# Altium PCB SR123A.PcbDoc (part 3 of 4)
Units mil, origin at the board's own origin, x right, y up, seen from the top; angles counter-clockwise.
Board outline 5500 x 3200 mil, 4 copper layers (Top Layer, Signal Layer 1, Signal Layer 2, Bottom Layer), stack 64.312 mil thick; 295 components, 105 nets, 659 pads, 1365 vias.
Unrouted connection lines stored in the file: 735.
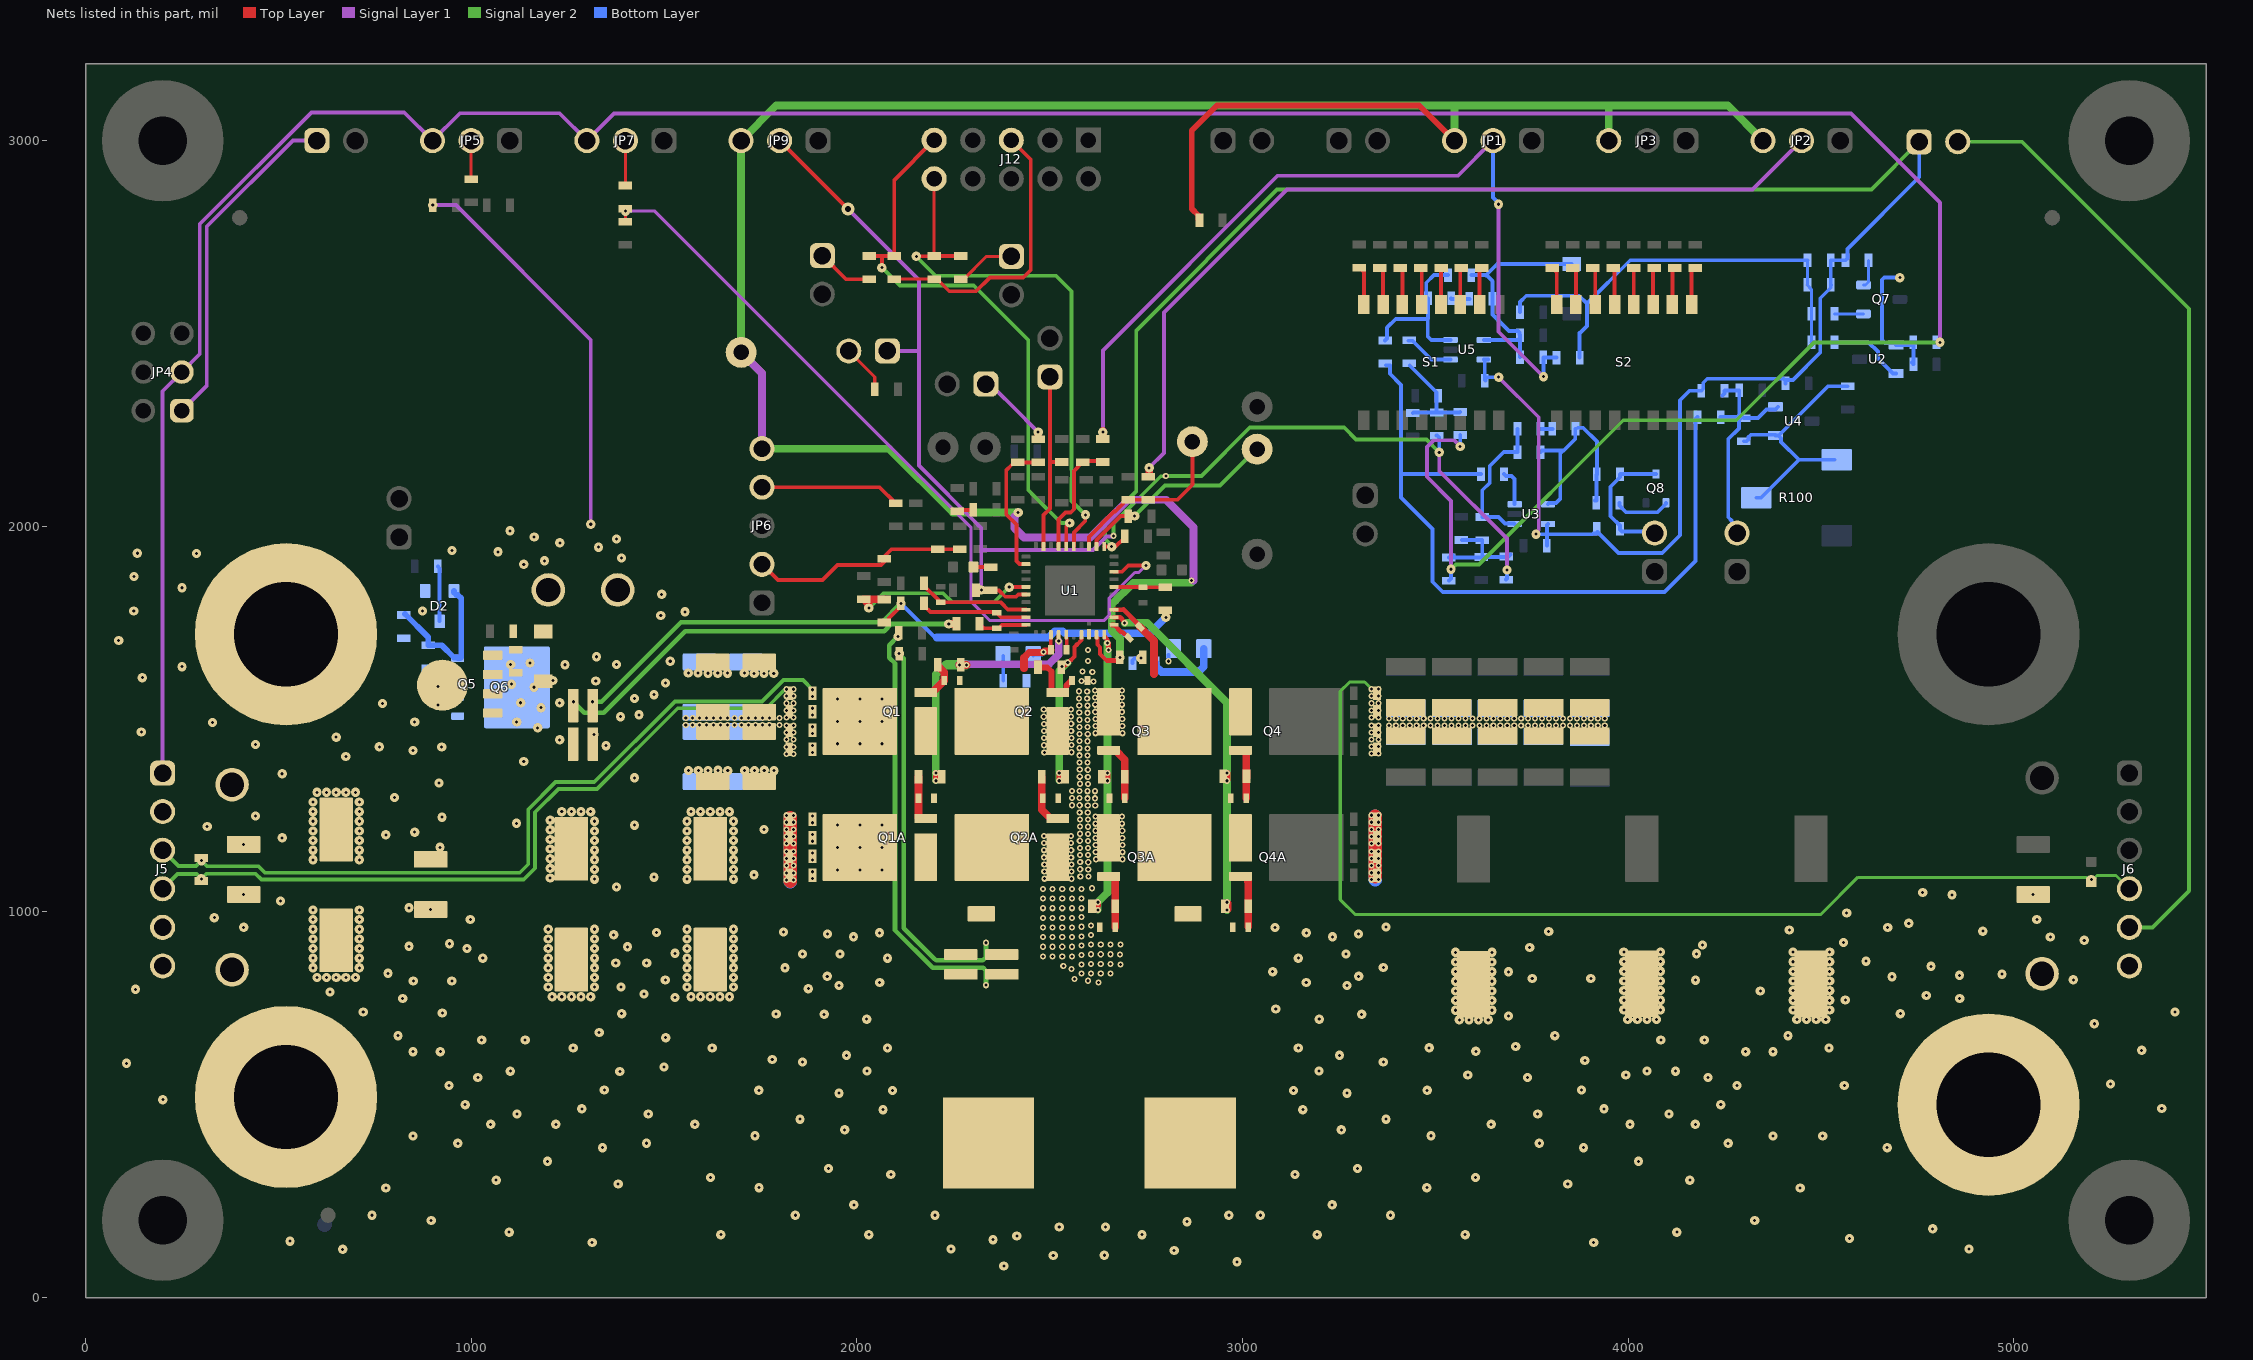
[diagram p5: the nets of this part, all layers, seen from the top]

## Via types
v1: diameter 24, hole 7.87, Top Layer to Bottom Layer, tented both sides, 520 vias
v2: diameter 16, hole 8, Top Layer to Bottom Layer, tented both sides, 418 vias
v3: diameter 24, hole 8, Top Layer to Bottom Layer, tented both sides, 412 vias
v4: diameter 19.68, hole 7.87, Top Layer to Bottom Layer, tented both sides, 12 vias
v5: diameter 16, hole 7.87, Top Layer to Bottom Layer, tented both sides, 2 vias
v6: diameter 34, hole 16, Top Layer to Bottom Layer, tented both sides, 1 vias

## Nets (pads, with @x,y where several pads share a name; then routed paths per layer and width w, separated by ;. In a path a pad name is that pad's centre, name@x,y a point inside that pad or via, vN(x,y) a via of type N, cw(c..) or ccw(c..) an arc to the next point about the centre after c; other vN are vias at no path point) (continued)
GND: C1.1 C2.1 C3.2 C4.2 C5.2 C6.2 C7.2 C8.2 C9.2 C10.2 C11.1 C12.1 C13.1 C14.1 C15.2 C16.2 C17.2 C18.2 C19.2 C20.2 C21.2 C22.2 C23.2 C24.2 C25.1 C26.1 C27.1 C28.1 C29.1 C30.1 C31.2 C32.1 C33.2 C38.1 C56.2 C57.2 C62.2 C63.2 C65.2 C66.2 C67.2 C68.2 C69.2 C70.2 C71.2 C72.2 C73.1 C74.1 C75.1 C76.1 C77.2 C78.1 C79.2 C80.2 C81.1 C82.2 C83.1 C84.1 C85.1 C86.1 J3.1 J4.1 J5.4 J5.5 J5.6 J6.4 J6.5 J6.6 J13.2 NT1.1 Q2.1-2-3 Q2A.1-2-3 Q3.1-2-3 Q3A.1-2-3 R59.1 R60.1 TP3.1 TP4.1 U1.28 | length 8172
  Top Layer w35: C72.2@1827.66,1080.02 C69.2@1827.66,1244.7 ; C86.1@3344.05,1090.88 C83.1@3344.05,1247.76
  Signal Layer 2 w8: v2(3335.03,1577.55) 3335.03,1578 3317.04,1595.99 3277.99,1595.99 3253.8,1571.8 3253.8,1031.76 3291.82,993.73 4500.21,993.73 4596.1,1089.63 5191.78,1089.63 5194.04,1087.37 5208.82,1087.37 5216.03,1094.58 5265.42,1094.58 J6.4@5300,1060
  Signal Layer 2 w10: J5.4@200,1060 238.72,1098.72 287.51,1098.72 296.45,1089.79 v3@298.57,1089.79 ; v3(300.37,1085.82) 313.5,1098.95 441.17,1098.95 456.38,1083.74 1136.51,1083.74 1165.82,1113.04 1165.82,1258.33 1226.42,1318.94 1326.71,1318.94 1535.9,1528.12 1765.18,1528.12 1813.36,1576.3 1816.82,1576.3 v2(1817.97,1577.45) ; J13.2@4855,2997 5022,2997 5455,2564 5455,1054.69 5360.31,960 J6.5@5300,960
  Signal Layer 2 w35: 1827.66,1084 1827.66,1239.65 ; 3344.05,1092.57 3344.05,1247.29
  Bottom Layer w10: R60.1@2715,1645 2715,1652.5 2720,1657.5 2735.71,1657.5 v3(2736.5,1658.29)
  Bottom Layer w35: 1827.66,1077.6 1827.66,1242.29 ; 3344.94,1083.73 3344.94,1248.41
  other v1: 2381.22,81.72 2986.22,92.72 2509.48,108.97 2641.99,109.69 2823.15,121.87 666.81,125 2244.33,125.76 4884.1,125.84 1313.97,142.68 3911.03,142.68 530.5,146.05 2353.42,150 4574.34,152.78 2415,159.39 1647.31,162.88 2031.16,162.88 2739.38,162.88 3193.84,162.88 3577.69,162.88 1098.48,169.61 4126.52,169.61 2525,183 2645.01,183 2856.22,196.72 896.46,199.92 4328.54,199.92 742.62,213.39 2202.79,213.39 2964.88,213.39 3046.49,213.39 1992.24,240.53 3232.76,240.53 778.61,284.09 4446.39,284.09 1746.69,284.82 3478.31,284.82 1381.32,294.2 3843.68,294.2 1064.81,304.3 4160.19,304.3 1620.38,311.03 3604.62,311.03 2088.4,318.88 3136.6,318.88 1926.78,334.6 3298.22,334.6 1198.11,353.33 4026.89,353.33 1340.54,388.47 3884.46,388.47 4671.98,388.47 965.44,400 4259.56,400 849.32,418.78 1735.81,419.5 3489.19,419.5 4375.68,418.78 4504.83,418.78 1968.62,434.98 3256.38,434.98 1050.61,449.08 1219.7,449.08 1579.97,449.08 3645.03,449.08 4005.3,449.08 4174.39,449.08 1852.7,462.55 3372.3,462.55 1118.69,476.02 1459.3,476.02 3765.7,476.02 4106.31,476.02 2068.2,487.23 3156.8,487.23 1287.04,489.49 3937.96,489.49 984.54,500 4240.46,500 200.53,513.05 1953.72,530 3271.28,530 1745.92,537.35 2092.5,536.62 3132.5,536.62 3479.08,537.35 1345.47,538.07 3879.53,538.07 942.62,550.09 4282.38,550.09 4560.87,550.09 5251.11,553.46 1017.39,570.29 3739.31,570.29 4207.61,570.29 3584.42,577.03 3994.2,577.03 1385.54,586.43 1101.66,587 4123.34,587 2026.49,587.72 3198.51,587.72 4048.87,587.72 106.25,607.33 1859.44,610.7 3365.56,610.7 3888.02,614.59 1780.81,617.46 1973.29,627.96 3251.71,627.96 849.32,637.64 920.03,637.64 3605.26,638.36 4304.97,637.64 4375.68,637.64 5331.92,641 1264.7,647.04 1624.97,647.04 2079.91,646.82 3145.09,646.82 4521.1,646.78 3484.38,647.54 3708.61,651 1027.15,667.72 1140.1,667.72 4084.9,667.72 4197.85,667.72 1504.3,673.98 810.19,678.97 3810.23,678.97 4414.81,678.97 1332.04,687.45 2025.72,721.81 3199.28,721.81 3690,730 1915.58,734.34 3309.42,734.34 1790.92,735.31 1390.47,736.03 4705.96,736.1 925.21,737.99 720.17,740.17 3086.48,748.01 4563.53,771.24 822.38,775.68 1528.45,777.78 4773.46,783.29 1448.39,787.2 633.83,792.52 4342.96,795.07 129.82,799.25 1874.48,801 1388.68,805 1953.72,809.36 3271.28,809.36 2059.44,817.2 3165.56,817.2 850.1,820.57 4175.03,822.92 1503.47,823.69 3751.61,827.2 3903.53,827.2 4684.37,831.85 1923.41,832.92 3301.59,832.92 4859.81,835.63 784.65,840.72 3078.42,845 3690,844.75 1813.97,855 3365.56,855.72 4785.38,858.79 1375,867.53 1455.19,867.53 4617.03,872.25 2079.91,880 3145.09,880 1859.44,890.72 1956.61,890.72 3268.39,890.72 4177.57,891.18 1528.45,892.54 3744.81,907.53 1405.69,909.38 838.93,910.72 4193.04,914.38 4558.6,920.84 1991.46,935.32 3233.54,935.32 1369.46,940.58 1924.19,942.54 3300.81,942.54 2059.17,945.72 3165.83,945.72 1480.76,946.61 1809.92,947.98 3794.31,949.38 4418.37,953.06 3084.59,959.38 410,960 4673.26,959.8 3372.3,960.89 4727.94,970.49 334.12,985.13 4567.09,997.36 838.93,1010.72 505.62,1028.16 410,1045.04 5050.72,1045.04 4763.97,1050.49
  other v2: 2626.91,817.29 2599.24,821.5 2564.6,826.41 2582.71,840.11 2607.71,840.11 2632.71,840.11 2657.71,840.11 2556.77,852.03 2535.53,860 2582.74,863.27 2683.73,863.63 2607.71,865.11 2632.71,865.11 2657.71,865.11 2482.79,884.61 2507.79,884.61 2532.79,884.61 2557.79,884.61 2582.74,888.27 2607.71,890.11 2632.71,890.11 2657.71,890.11 2682.52,889.82 2482.79,909.61 2507.79,909.61 2532.79,909.61 2557.79,909.61 2582.74,913.27 2607.71,915.11 2632.71,915.11 2657.71,915.11 2683.73,915.21 2482.79,934.61 2507.79,934.61 2532.79,934.61 2557.79,934.61 2582.76,936.44 2607.71,940.11 2482.79,959.61 2507.79,959.61 2532.79,959.61 2557.79,959.61 2582.76,961.44 2607.71,965.11 2482.79,984.61 2507.79,984.61 2532.79,984.61 2557.79,984.61 2582.76,986.44 2482.79,1009.61 2507.79,1009.61 2532.79,1009.61 2557.79,1009.61 2582.79,1009.61 2482.79,1034.61 2507.79,1034.61 2532.79,1034.61 2557.79,1034.61 2582.79,1034.61 2482.79,1059.61 2507.79,1059.61 2532.79,1059.61 2557.79,1059.61 2582.79,1059.61 2609.87,1061.43 1817.97,1082.45 1835.97,1082.45 3335.03,1083.55 3353.03,1083.55 2486.69,1086.19 2556.89,1085.97 2579.71,1092.24 2600.69,1091.79 1817.97,1100.45 1835.97,1100.45 3335.03,1101.55 3353.03,1101.55 2556.48,1104.42 2486.28,1104.64 2600.28,1110.25 2579.3,1110.7 1817.97,1120 1835.97,1120 3335.03,1120 3353.03,1120 2486.28,1123.13 2556.48,1122.91 2579.3,1129.18 2600.28,1128.74 2620.17,1136.46 2689.29,1136.46 1817.97,1138.45 1835.97,1138.45 3335.03,1138.55 3353.03,1138.55 2555.96,1141.37 2485.76,1141.59 2599.76,1147.19 2578.77,1147.64 2619.76,1154.92 2688.88,1154.91 1817.97,1156.45 1835.97,1156.45 3335.03,1156.55 3353.03,1156.55 2485.76,1160.07 2555.96,1159.86 2578.77,1166.13 2599.76,1165.68 2619.76,1173.41 2688.88,1173.4 1817.97,1177.45 1835.97,1177.45 2555.55,1178.31 3335.03,1177.55 3353.03,1177.55 2485.35,1178.53 2599.35,1184.14 2578.36,1184.58 2619.24,1191.86 2688.36,1191.86 1817.97,1195.45 1835.97,1195.45 3335.03,1195.55 3353.03,1195.55 2485.35,1197.02 2555.55,1196.8 2599.94,1202.26 2578.95,1202.71 2619.24,1210.35 2688.36,1210.35 1817.97,1214 1835.97,1214 3335.03,1214 3353.03,1214 2578.54,1221.16 2599.53,1220.72 2618.83,1228.81 2687.95,1228.8 1817.97,1232.45 1835.97,1232.45 3335.03,1232.55 3353.03,1232.55 2599.53,1239.2 2578.54,1239.65 2618.83,1247.29 2687.95,1247.29 1817.97,1250.45 1835.97,1250.45 3335.03,1250.55 3353.03,1250.55 2578.02,1258.11 2599.01,1257.66 2599.01,1276.15 2618.29,1276.15 2558.2,1276.59 2578.02,1276.59 2557.79,1295.05 2577.61,1295.05 2598.6,1294.61 2617.88,1294.61 2598.6,1313.09 2617.88,1313.09 2557.79,1313.54 2577.61,1313.54 2578.53,1332.23 2599.52,1331.79 2599.11,1350.24 2578.12,1350.69 2578.12,1369.18 2599.11,1368.73 2598.59,1387.19 2577.6,1387.63 2577.6,1406.12 2598.59,1405.68 1817.97,1409.45 1835.97,1409.45 3335.03,1410.55 3353.03,1410.55 2486.27,1413.7 2556.93,1413.99 2598.18,1424.13 2577.19,1424.58 1817.97,1427.45 1835.97,1427.45 3335.03,1428.55 3353.03,1428.55 2485.86,1432.16 2556.52,1432.45 2577.19,1443.07 2598.18,1442.62 1817.97,1447 1835.97,1447 3335.03,1447 3353.03,1447 2485.86,1450.64 2556.52,1450.94 2577.86,1461.28 2598.84,1460.83 2619.22,1463.46 2688.74,1463.46 1817.97,1465.45 1835.97,1465.45 3335.03,1465.55 3353.03,1465.55 2485.34,1469.1 2556,1469.4 2598.43,1479.29 2577.45,1479.74 2618.81,1481.92 2688.33,1481.92 1817.97,1483.45 1835.97,1483.45 1556.46,1484.45 1574.52,1484.45 1592.59,1484.45 1610.65,1484.45 1628.71,1484.45 1646.77,1484.45 1664.83,1484.45 1682.9,1484.45 1700.96,1484.45 1719.02,1484.45 1737.08,1484.45 1755.14,1484.45 1773.21,1484.45 1799.9,1484.45 3335.03,1483.55 3353.03,1483.55 3379.73,1483.55 3397.79,1483.55 3415.85,1483.55 3433.92,1483.55 3451.98,1483.55 3470.04,1483.55 3488.1,1483.55 3506.16,1483.55 3524.23,1483.55 3542.29,1483.55 3560.35,1483.55 3578.41,1483.55 3596.47,1483.55 3614.54,1483.55 3632.6,1483.55 3650.66,1483.55 3668.72,1483.55 3686.78,1483.55 3704.85,1483.55 3722.91,1483.55 3740.97,1483.55 3759.03,1483.55 3777.09,1483.55 3795.16,1483.55 3813.22,1483.55 3831.28,1483.55 3849.34,1483.55 3867.4,1483.55 3885.47,1483.55 3903.53,1483.55 3921.59,1483.55 3939.65,1483.55 2485.34,1487.59 2556,1487.88 2577.45,1498.22 2598.43,1497.78 2618.81,1500.4 2688.33,1500.4 1556.46,1502.45 1574.53,1502.45 1592.59,1502.45 1610.65,1502.45 1628.71,1502.45 1646.77,1502.45 1664.84,1502.45 1682.9,1502.45 1700.96,1502.45 1719.02,1502.45 1737.08,1502.45 1755.15,1502.45 1773.21,1502.45 1799.91,1502.45 3379.73,1501.55 3397.79,1501.55 3415.86,1501.55 3433.92,1501.55 3451.98,1501.55 3470.04,1501.55 3488.1,1501.55 3506.17,1501.55 3524.23,1501.55 3542.29,1501.55 3560.35,1501.55 3578.41,1501.55 3596.48,1501.55 3614.54,1501.55 3632.6,1501.55 3650.66,1501.55 3668.72,1501.55 3686.79,1501.55 3704.85,1501.55 3722.91,1501.55 3740.97,1501.55 3759.03,1501.55 3777.1,1501.55 3795.16,1501.55 3813.22,1501.55 3831.28,1501.55 3849.34,1501.55 3867.41,1501.55 3885.47,1501.55 3903.53,1501.55 3921.59,1501.55 3939.65,1501.55 1817.97,1504.45 1835.97,1504.45 3335.03,1504.55 3353.03,1504.55 2484.93,1506.05 2555.59,1506.34 2597.91,1516.23 2576.93,1516.68 2618.29,1518.86 2687.81,1518.86 1817.97,1522.45 1835.97,1522.45 3335.03,1522.55 3353.03,1522.55 2484.93,1524.53 2555.59,1524.83 2576.93,1535.17 2597.91,1534.72 2618.29,1537.35 2687.81,1537.35 1817.97,1541 1835.97,1541 3335.03,1541 3353.03,1541 2597.5,1553.18 2576.52,1553.62 2617.88,1555.8 2687.4,1555.8 1817.97,1559.45 1835.97,1559.45 3335.03,1559.55 3353.03,1559.55 2576.52,1572.11 2597.5,1571.67 2617.88,1574.29 2687.4,1574.29 1835.97,1577.45 3353.03,1577.55 2582.5,1598.38 2614.13,1597.9 2610.83,1622.29 2585.69,1623.41
  other v3: 4790,178.09 1840.7,213.39 3384.3,213.39 1455,400 3770,400 5383.92,490 1500,597.96 5209.27,710 3562.49,720.07 3587.49,720.07 3612.49,720.07 3637.49,720.07 3999.13,720.95 4024.13,720.95 4049.13,720.95 4074.13,720.95 4437.76,720.74 4462.76,720.74 4487.76,720.74 4512.76,720.74 5418.68,740.17 3552.49,745.07 3647.49,745.07 3989.13,745.95 4084.13,745.95 4427.76,745.74 4522.76,745.74 3552.49,770.07 3647.49,770.07 3989.13,770.95 4084.13,770.95 4427.76,770.74 4522.76,770.74 4860,775.68 1210,780 1235,780 1260,780 1285,780 1310,780 1570,780 1595,780 1620,780 1645,780 1670,780 3552.49,795.07 3647.49,795.07 3989.13,795.95 4084.13,795.95 4427.76,795.74 4522.76,795.74 1200,805 1320,805 1560,805 1680,805 3552.49,820.07 3647.49,820.07 949.88,820.57 3989.13,820.95 4084.13,820.95 4427.76,820.74 4522.76,820.74 5154.65,823.83 600,830 625,830 650,830 675,830 700,830 1200,830 1320,830 1560,830 1680,830 4970,838.59 3552.49,845.07 3647.49,845.07 3989.13,845.95 4084.13,845.95 4427.76,845.74 4522.76,845.74 590,855 710,855 1200,855 1320,855 1560,855 1680,855 3552.49,870.07 3647.49,870.07 3989.13,870.95 4084.13,870.95 4427.76,870.74 4522.76,870.74 590,880 710,880 1030,880 1200,880 1320,880 1560,880 1680,880 3552.49,895.07 3647.49,895.07 3989.13,895.95 4084.13,895.95 4427.76,895.74 4522.76,895.74 590,905 710,905 989.35,905 1200,905 1320,905 1560,905 1680,905 943.56,917.53 5183.02,926.3 590,930 710,930 1200,930 1320,930 1560,930 1680,930 5095,935 4920,950 590,955 710,955 1200,955 1320,955 1560,955 1680,955 590,980 710,980 997.93,980 5060,980 590,1005 710,1005 895,1006.27 4840,1044.28 5201.43,1084.31
  other v5: 2599.26,1650.45 2600,1678.86
HB1: C39.2 U1.25 | length 34.2
  Top Layer w10: U1.25@2543.24,1712.02 2544.6,1710.65 C39.2@2544.6,1680.46 ; C39.2@2544.06,1679.57 2543.73,1679.24 C39.2@2544.86,1680.37
HB2: C40.2 U1.31 | length 56.9
  Top Layer w12: U1.31@2661,1744 2667.59,1744 2686.3,1725.29 2690.19,1725.29 2703.34,1712.14 C40.2@2704.68,1712.14
HO1: R11.1 R61.1 U1.24 | length 748.9
  Top Layer w10: R61.1@2213.36,1350.64 2205,1342.28 R61.1@2220,1350 ; U1.24@2523.47,1718.83 2523.55,1718.75 2523.55,1702.16 v2(2523.73,1701.99)
  Top Layer w15: v2@2205,1342.28 v2(2205,1360)
  Top Layer w20: v2(2265.93,1640.48) v2@2284.35,1640.48
  Signal Layer 1 w20: v2@2265.93,1642.11 2284.51,1642.11 2498.33,1642.11 2523.73,1667.51 v2(2523.73,1701.99)
  Signal Layer 2 w10: 2231.39,1642.11 2233.01,1640.48
  Signal Layer 2 w20: v2@2205,1341.18 v2(2205,1360) 2205,1615.72 2231.39,1642.11
  Signal Layer 2 w25: 2233.01,1640.48 v2(2265.93,1640.48) v2@2283.21,1640.48
  other v2: 2205,1340 2284.51,1640.64
HO1_G: C55.1 Q1.4 R11.2 | length 112.7
  Top Layer w20: Q1.4@2178.9,1569 2196.61,1569 2198.43,1570.81 2198.43,1571.53 C55.1@2227.09,1600.2 2227.09,1621.8 2215.37,1633.52 2209.9,1633.52 R11.2@2209.9,1641.02
HO2: R14.1 R36.1 U1.32 | length 981.4
  Top Layer w10: U1.32@2667.17,1764.1 U1.32@2667.25,1764.02 ; 2680.79,1764.02 2680.98,1763.83 ; R14.1@2950.59,1351.86 v2@2962,1341.42
  Top Layer w11: U1.32@2667.25,1764.02 2680.79,1764.02
  Top Layer w12: 2680.98,1763.83 2682.96,1763.83 2694,1752.79 2694,1749.98 v2(2694.76,1749.22)
  Top Layer w15: v2@2962,1341.42 v2@2962,1360.76
  Top Layer w20: R36.1@2955,1015 R36.1@2955,1022.36 ; R36.1@2962,1007.64 R36.1@2962,1022.36
  Signal Layer 2 w20: v2(2694.76,1749.22) 2695.46,1749.91 2752.84,1749.91 2960,1542.75 v2(2960,1025) v2(2960,1005)
  other v2: 2960,1340 2960,1360
HO2_G: C58.2 Q4.4 R14.2 | length 138.1
  Top Layer w20: Q4.4@2995.1,1419 3008.19,1419 3010,1417.19 3010,1365.81 3010.59,1365.22 R14.2@3010.59,1348.4 ; C58.2@3010,1295 R14.2@3010,1348.4
ILIMCOMP: C45.1 JP9.2 JP10.1 R56.2 R79.2 R94.2 U1.16 | length 3417.5
  Top Layer w10: JP9.2@1800,3000 v6(1977.44,2822.56) ; C45.1@2309.35,1834.12 R56.2@2347.75,1834.12 2368.48,1834.12 2370.51,1832.09 2370.51,1831.89 2385.08,1817.32 2412.73,1817.32 2418.56,1823.16 U1.16@2438.83,1823.16
  Signal Layer 1 w10: v6(1977.44,2822.56) 2161.08,2638.92 2161.08,2454.69 ; JP10.1@2079.27,2454.69 2161.08,2454.69 ; v1(2322.86,1834.45) 2322.86,1938.05 ; v2@2664.71,1974.26 2663.57,1973.11 2647.55,1973.11 2612.48,1938.05 2322.86,1938.05 ; v1(3510.4,2191.74) 3510.4,2143.71 3686.21,1967.9 v1(3686.21,1886.67) ; 2161.08,2454.69 2161.08,2157.46 2314.6,2003.94 2314.6,2003.4 2322.86,1995.15 2322.86,1938.05
  Signal Layer 2 w10: v2(2665.31,1975.22) 2665.31,2006.58 2671.11,2012.38 2788.33,2129.6 2800.21,2129.6 v2(2801.36,2130.75) 2893.97,2130.75 3019.1,2255.87 3263.95,2255.87 3294.68,2225.14 3477,2225.14 v1(3510.4,2191.74)
  Bottom Layer w10: R94.2@3503.34,2235.08 3505.4,2235.08 3510.4,2230.08 v1(3510.4,2191.74) ; R79.2@3683.97,1861.54 3686.21,1863.78 v1(3686.21,1886.67)
ISNSN: C49.1 R6.1 U1.19 | length 282.9
  Top Layer w10: R6.1@2174.38,1800 2174.38,1793.86 2190.87,1777.37 2361.06,1777.37 C49.1@2362.79,1775.65 2374.33,1764.1 U1.19@2438.83,1764.1
ISNSP: C49.2 R5.1 U1.20 | length 128.8
  Top Layer w10: R5.1@2318.38,1747 2329.73,1735.65 C49.2@2362.79,1735.65 2368.01,1735.65 2376.78,1744.42 U1.20@2438.83,1744.42
LO1: R12.1 R62.1 U1.27 | length 457.2
  Top Layer w10: v2@2525,1342.28 2533.86,1351.14 v2(2525,1360) ; 2571.71,1693.9 2582.53,1704.73 U1.27@2582.53,1712.02
  Top Layer w11: v2(2547.06,1646.28) 2548.12,1646.28 2556.01,1654.16 2556.77,1654.16 2564.6,1662 2564.6,1686.8 2571.71,1693.9
  Top Layer w15: v2@2525,1342.28 v2(2525,1360) ; R12.1@2533,1635 2540,1642 2540,1641.6 2542.5,1644.1 2544.62,1644.1 2546.79,1646.28 v2(2547.06,1646.28)
  Signal Layer 2 w20: v2@2525,1342.28 v2(2525,1360) 2525,1625 2546.28,1646.28 v2(2547.06,1646.28)
  other v2: 2525,1340 2531.69,1636.61
LO1_G: C56.1 Q2.4 R12.2 | length 164.7
  Top Layer w15: R12.2@2470,1634.1 2494.07,1634.1 2504.63,1623.54 2504.63,1573.31 2508.94,1569 2538.61,1569 2542.93,1573.31 2542.93,1586.71 2551.71,1595.5 2555,1595.5 C56.1@2555,1600
LO2: R13.1 R63.1 U1.30 | length 790.6
  Top Layer w10: R13.1@2644.68,1340.32 v2@2650,1340.32
  Top Layer w12: U1.30@2642.66,1713.02 2649.67,1706.01 v2(2649.67,1696.91) v2@2648.9,1697.68 ; v2@2652.63,1679.24 2652.67,1679.29 v2@2652.67,1697.88
  Top Layer w15: v2(2625,1005.32) 2618.48,1011.83 2615.16,1015.16 v2(2625,1025) ; v2@2650,1340.32 v2(2650,1360)
  Signal Layer 2 w20: v2(2625,1005.32) v2(2625,1025) 2650,1050 2650,1340.32 v2@2650,1676.61 ; v2@2649.67,1679.58 v2(2649.67,1696.91)
  other v2: 2650,1340 2652.63,1679
LO2_G: C57.1 Q3.4 R13.2 | length 151.7
  Top Layer w20: Q3.4@2653.1,1419 2670.82,1419 2695,1394.82 R13.2@2695,1350 C57.1@2695,1295
MODE: C52.1 R22.2 U1.7 | length 305.2
  Top Layer w10: U1.7@2523.47,1947.17 2523.47,2017.67 2535.88,2030.07 2541.68,2035.87 2554.72,2035.87 2562.84,2044 2562.84,2143.53 C52.1@2585.69,2166.38 ; C52.1@2585.69,2169.38 2637.96,2169.38 R22.2@2638.15,2169.57
MODE1: JP1.2 R22.1 R67.1 R75.1 | length 2217.1
  Top Layer w8: R22.1@2638.15,2229.57 R22.1@2638.59,2229.13
  Top Layer w20: R22.1@2638.15,2229.57 v1@2638.15,2246.91
  Signal Layer 1 w10: v1(2638.15,2243.91) 2638.15,2456.08 3090.96,2908.89 3558.89,2908.89 JP1.2@3650,3000 ; v3(3664.21,2834.97) 3664.21,2504.54 v1(3780.95,2387.8)
  Bottom Layer w10: JP1.2@3650,3000 3650,2852.97 3664.21,2838.76 v3(3664.21,2834.97) ; R67.1@3780.48,2438.06 3780.48,2388.27 v1(3780.95,2387.8) ; R67.1@3782.03,2438.5 3783.03,2437.5 R75.1@3814.53,2437.5
NetC3_1: C3.1 C4.1 C5.1 C6.1 C7.1 C8.1 C9.1 C10.1 C25.2 C26.2 C31.1 C65.1 C66.1 C67.1 C68.1 C69.1 C70.1 C71.1 C72.1 J5.3 Q1.5-6-7-8 Q1A.5-6-7-8 R1.2 R2.2 R6.2 R9.2 R15.2 R34.2 TP8.1 | length 4797.6
  Top Layer w10: R9.2@2071.17,1750.32 2078.67,1750.32 2083.67,1755.32 2083.67,1761.79 2114.38,1792.5 v1(2114.38,1800)
  Top Layer w20: v1(2801.36,1763.92) R34.2@2801.36,1780.84
  Signal Layer 1 w10: v3(900.36,2832.68) 960.36,2832.68 1310.08,2482.95 v3(1310.08,2005.2)
  Signal Layer 2 w10: J5.3@200,1160 241.28,1118.72 286.65,1118.72 v3(300.78,1132.86) 315.29,1118.35 448.57,1118.35 465.31,1101.61 1126.13,1101.61 1147.94,1123.42 1147.94,1265.73 1219.02,1336.81 1319.31,1336.81 1528.49,1545.99 1754.53,1545.99 1809.61,1601.07 1860.23,1601.07 v2(1885.18,1576.12)
  Signal Layer 2 w12: v3(1315,1545) 1337.91,1545 1544.23,1751.32 2065.69,1751.32 v1(2114.38,1800)
  Bottom Layer w10: v1(2114.38,1800) 2203.04,1711.33 2207.67,1711.33
  Bottom Layer w20: 2207.67,1711.33 2496.48,1711.33 2513.01,1727.86 2534.44,1727.86 2539.52,1722.79 2760.23,1722.79 v1(2801.36,1763.92)
  other v1: 1377.21,1064.39 1474.3,1090 1733.39,1096.1 1759.38,1214 1423.63,1224.87
  other v2: 1885.18,1086.12 1885.18,1104.12 1885.18,1135.12 1885.18,1153.12 1885.18,1183.12 1885.18,1201.12 1885.18,1231.12 1885.18,1249.12 1885.18,1413.12 1885.18,1431.12 1885.18,1462.12 1885.18,1480.12 1885.18,1510.12 1885.18,1528.12 1885.18,1558.12
  other v3: 1320,1085 1560,1085 1680,1085 1205,1087.91 1950.16,1109.13 2008.03,1109.13 2065.91,1109.13 1320,1110 1560,1110 1680,1110 1205,1112.91 1320,1135 1560,1135 1680,1135 1205,1137.91 1320,1160 1560,1160 1680,1160 1205,1162.91 1950.16,1167 2008.03,1167 2065.91,1167 1320,1185 1560,1185 1680,1185 1205,1187.91 1320,1210 1560,1210 1680,1210 1205,1212.91 1950.16,1224.87 2008.03,1224.87 2065.91,1224.87 1320,1235 1560,1235 1680,1235 1205,1237.91 1235,1260 1260,1260 1285,1260 1310,1260 1570,1260 1595,1260 1620,1260 1645,1260 1670,1260 1423.63,1347.62 1665.43,1366.2 1785.43,1366.2 1563.86,1366.94 1589.16,1366.94 1614.46,1366.94 1639.94,1367.13 1709.16,1366.94 1734.46,1366.94 1759.94,1367.13 1349.69,1431.12 1950.16,1436.13 2008.03,1436.13 2065.91,1436.13 1318.54,1459.82 1950.16,1494 2008.03,1494 2065.91,1494 1387.04,1506.22 1435,1511.03 1950.16,1551.87 2008.03,1551.87 2065.91,1551.87 1423.63,1553.23 1474.3,1563.24 1504.28,1593.64 1323.18,1598.59 1733.9,1618.38 1614.06,1618.87 1639.54,1619.06 1664.84,1619.06 1708.41,1619.31 1759.38,1618.56 1784.68,1618.56 1563.27,1619.8 1588.57,1619.8 1376.98,1641.81 1516.34,1649.96 1325,1661.68 1491.71,1768.7 1554.27,1778.23 1493.96,1823.54 1390,1917.71 1330.15,1945.95 1377.21,1967.19
NetC34_2: C34.2 R34.1 U1.36 | length 133.5
  Top Layer w10: U1.36@2667.17,1842.84 2741.47,1842.84 C34.2@2742.37,1841.95 R34.1@2800.28,1841.92
NetC35_1: C35.1 R35.1 U1.18 | length 291.6
  Top Layer w10: R35.1@2174.47,1852.68 2174.47,1844.92 2186.39,1833 2186.65,1833 2189.28,1830.37 2189.71,1830.37 2197.25,1822.83 C35.1@2216.93,1803.16 ; C35.1@2222.79,1803.16 2372.95,1803.16 2380.08,1796.02 2387.66,1788.48 ; 2387.66,1788.44 2392.32,1783.79 U1.18@2438.83,1783.79
NetC42_1: C42.1 R32.1 | length 37.6
  Top Layer w10: C42.1@2264.56,2042.59 R32.1@2302.19,2042.59
NetC46_1: C46.1 R56.1 | length 45.5
  Top Layer w10: C46.1@2302.69,1894.12 R56.1@2347.75,1894.12 ; C46.1@2312.38,1894.43 C46.1@2312.69,1894.12
NetC50_1: C50.1 JP6.2 R19.1 R20.2 | length 570.6
  Top Layer w10: JP6.2@1754.31,1901.32 1795.25,1860.37 1911.32,1860.37 1950.45,1899.51 2062.86,1899.51 2072.77,1909.41 2072.77,1923.56 2089.63,1940.42 C50.1@2209.91,1940.42 R20.2@2266.51,1940.42
NetC59_1: C59.1 R59.2 | length 63.6
  Bottom Layer w10: R59.2@2380,1600 C59.1@2380,1663.57
NetC60_1: C60.1 R60.2 | length 190.7
  Bottom Layer w20: R60.2@2775,1645 2775,1637.5 2790.37,1622.13 2885.74,1622.13 2899.7,1636.09 C60.1@2899.7,1682.46
NetC61_1: C61.1 Q1A.4 R61.2 | length 125.8
  Top Layer w20: R61.2@2160,1350 2160,1243.81 2161.81,1242 Q1A.4@2178.9,1242
NetC62_1: C62.1 Q2A.4 R62.2 | length 135.3
  Top Layer w20: R62.2@2480,1350 2480,1295 2480,1265.18 2503.18,1242 Q2A.4@2520.9,1242
NetC63_1: C63.1 Q3A.4 R63.2 | length 147.8
  Top Layer w20: Q3A.4@2653.1,1092 2668.19,1092 2670,1090.19 R63.2@2670,1015 C63.1@2670,960
NetC64_2: C64.2 Q4A.4 R36.2 | length 148.6
  Top Layer w20: Q4A.4@2995.1,1092 3012.82,1092 3014.63,1090.19 3014.63,1078.84 3015,1078.47 3015,1028.36 3015,1002 C64.2@3015,962
NetC87_1: C87.1 D2.2 Q6.4 R58.1 | length 388.6
  Bottom Layer w15: C87.1@828.43,1772.55 888.6,1712.39 R58.1@888.6,1691.7 923.95,1691.7 955.61,1660.04 962.5,1660.04 Q6.4@965.04,1657.5 971.62,1657.5 974.16,1660.04 974.16,1813.31 965.37,1822.09 961.85,1822.09 955.57,1828.37 D2.2@955.57,1832.31
NetC88_2: C88.2 D2.3 | length 144
  Bottom Layer w10: C88.2@913.6,1895.71 918.17,1891.14 D2.3@918.17,1753.57
NetC89_2: C89.2 R71.1 R72.2 R73.2 R74.2 R75.2 | length 1200.6
  Bottom Layer w8: C89.2@4465.53,2689.74 4465.53,2627.5 4464.04,2626 4475.53,2614.5 R73.2@4475.53,2550.81 4475.53,2478.5 R72.2@4474.04,2477
  Bottom Layer w10: R74.2@3720.01,2555 3720.01,2582 3735.94,2597.93 3873.6,2597.93 3893.78,2577.76 ; R75.2@3874.53,2437.5 3874.53,2501 ; 3875.03,2501 3893.78,2519.74 3893.78,2577.76 ; C89.2@4465.53,2689.74 4005.76,2689.74 3893.78,2577.76
NetC91_1: C91.1 R81.2 R84.1 U3.1 | length 378.5
  Bottom Layer w10: U3.1@3705.87,2005.92 3704.61,2007.18 3680.5,2007.18 3663.68,2024 R81.2@3622.03,2024 3622.03,2093.29 3641.41,2112.67 3641.41,2155.87 3677.74,2192.2 R84.1@3713.14,2192.2 C91.1@3713.14,2252.71
NetC91_2: C91.2 R83.2 | length 30.7
  Bottom Layer w10: C91.2@3773.14,2252.71 R83.2@3803.8,2252.71
NetC95_1: C95.1 R97.2 R99.1 U5.3 | length 418.7
  Bottom Layer w10: R97.2@3370.03,2482 3375.03,2487 3375.03,2515 3397.53,2537.5 3480.53,2537.5 ; R99.1@3533.35,2651.3 3496.7,2651.3 3476.84,2631.43 3476.84,2595.13 C95.1@3481.23,2590.74 3481.23,2538.19 3480.53,2537.5 ; U5.3@3539.73,2483.38 3489.57,2483.38 3480.53,2492.42 3480.53,2537.5
NetC95_2: C95.2 R98.2 | length 47.7
  Bottom Layer w10: C95.2@3541.23,2590.74 3542.17,2589.8 R98.2@3588.52,2589.8
NetD1_2: D1.2 Q5.4 R38.2 R39.1
NetD3_1: D3.1 R66.2 R67.2 R98.1 R99.2 U5.4 | length 629.9
  Bottom Layer w10: R99.2@3593.35,2651.3 3632.81,2651.3 3648.52,2635.58 R98.1@3648.52,2589.8 3648.52,2549.01 3691.33,2506.21 3715.01,2506.21 3718.53,2502.68 R66.2@3718.53,2497.5 ; U5.4@3626.34,2483.38 3715.01,2483.38 R66.2@3720.01,2488.38 ; 3631.03,2650 3661,2679.97 D3.1@3853.53,2679.97 ; R67.2@3720.01,2438.95 3720.01,2483.38 R66.2@3720.01,2495.58
NetJ10_1: J10.1 R25.2 | length 205.9
  Top Layer w20: R25.2@2470.36,2225.85 v1(2470.36,2244.37)
  Signal Layer 1 w10: J10.1@2334.52,2368.9 2355.06,2348.36 2366.37,2348.36 2404.73,2310 v1(2470.36,2244.37)
NetJ16_2: J16.2 Q8.3 R85.1 R87.2 | length 350.7
  Bottom Layer w10: J16.2@4068.96,1982.51 4064.98,1986.48 3984.16,1986.48 3979.16,1991.48 R87.2@3979.16,1994.11 3979.16,2001.61 3954.8,2025.97 3954.8,2102.65 3979.16,2127.01 R85.1@3979.16,2134.51 3980.47,2135.81 Q8.3@4072.59,2135.81
NetJP5_2: JP5.2 R16.2 | length 100
  Top Layer w8: R16.2@1000,2900 JP5.2@1000,3000
NetJP7_2: JP7.2 R37.2 | length 116.3
  Top Layer w8: R37.2@1400,2883.75 JP7.2@1400,3000
NetJP10_2: JP10.2 R26.2 | length 126.8
  Top Layer w8: JP10.2@1979.27,2454.69 2046.66,2387.3 R26.2@2046.66,2355.82
NetJP11_1: JP11.1 R27.1 | length 147.3
  Top Layer w10: JP11.1@1910.65,2702 1971.91,2640.73 R27.1@2032.57,2640.73
NetJP12_1: JP12.1 R28.1 | length 156.9
  Top Layer w8: R28.1@2269.93,2640.85 2277.43,2640.85 2336.52,2699.94 JP12.1@2401.09,2699.94 JP12.1@2400.18,2700.85
NetL1_1: L1.1 R3.2 R4.2 R8.2 | length 1094.1
  Signal Layer 2 w12: v3(2106.66,1714.26) 2084.13,1691.73 2084.13,1659.28 2099.04,1644.37 2099.04,952.73 2196.76,855 2327.45,855 2335,847.45 v2(2335,810)
NetQ7_1: Q7.1 R73.1 | length 74.9
  Bottom Layer w8: R73.1@4535.53,2550.81 Q7.1@4610.4,2550.81
NetQ7_2: Q7.2 R76.2 | length 72.9
  Bottom Layer w8: Q7.2@4610.4,2625.62 4615.99,2625.62 4623.66,2633.28 R76.2@4623.66,2689.74
NetQ8_1: Q8.1 R86.2 | length 146.8
  Bottom Layer w10: R86.2@3977.68,2061.01 3977.68,2053.51 3994.86,2036.32 4076.05,2036.32 4098.18,2058.45 Q8.1@4098.18,2061.01
NetR9_1: R9.1 R10.2 U1.15 | length 528.6
  Top Layer w10: v1(2395.38,1842.19) 2396.03,1842.84 U1.15@2438.83,1842.84
  Top Layer w20: R10.2@2017.44,1811.01 R10.2@2024.94,1811.01 ; v1(2031.26,1788.24) 2030.49,1789 2030.49,1797.96 2024.94,1803.51 R10.2@2024.94,1811.01 ; R9.1@2071.17,1811.13 2025.06,1811.13 R10.2@2024.94,1811.01
  Signal Layer 2 w10: v1(2031.26,1788.24) 2069.43,1826.4 2223.76,1826.4 2247,1803.16 2356.34,1803.16 v1(2395.38,1842.19)
NetR40_2: R40.2 S1.2 | length 97.5
  Top Layer w10: S1.2@3615,2575 3615,2664 R40.2@3621,2670
NetR41_2: R41.2 S1.3 | length 96.2
  Top Layer w10: S1.3@3565,2575 3565,2667 R41.2@3568,2670
NetR42_2: R42.2 S1.4 | length 95
  Top Layer w10: S1.4@3515,2575 R42.2@3515,2670
NetR43_2: R43.2 S1.5 | length 96.2
  Top Layer w10: R43.2@3462,2670 3465,2667 S1.5@3465,2575
NetR44_2: R44.2 S1.6 | length 97.5
  Top Layer w10: R44.2@3409,2670 3415,2664 S1.6@3415,2575
NetR45_2: R45.2 S1.7 | length 98.7
  Top Layer w10: R45.2@3356,2670 3365,2661 S1.7@3365,2575
NetR46_2: R46.2 S1.8 | length 100.2
  Top Layer w10: R46.2@3303.61,2670.47 3315,2659.08 S1.8@3315,2575
NetR47_2: R47.2 S2.1 | length 98.7
  Top Layer w10: S2.1@4165,2575 4165,2661 R47.2@4174,2670
NetR48_2: R48.2 S2.2 | length 97.5
  Top Layer w10: S2.2@4115,2575 4115,2664 R48.2@4121,2670
NetR49_2: R49.2 S2.3 | length 96.2
  Top Layer w10: S2.3@4065,2575 4065,2667 R49.2@4068,2670
NetR50_2: R50.2 S2.4 | length 95
  Top Layer w10: S2.4@4015,2575 R50.2@4015,2670
NetR51_2: R51.2 S2.5 | length 96.2
  Top Layer w10: R51.2@3962,2670 3965,2667 S2.5@3965,2575
NetR52_2: R52.2 S2.6 | length 97.5
  Top Layer w10: R52.2@3909,2670 3915,2664 S2.6@3915,2575
NetR53_2: R53.2 S2.7 | length 98.7
  Top Layer w10: R53.2@3856,2670 3865,2661 S2.7@3865,2575
NetR54_2: R54.2 S2.8 | length 100
  Top Layer w10: R54.2@3803,2670 3815,2658 S2.8@3815,2575
NetR69_1: R69.1 R70.2 U2.1 | length 358.2
  Bottom Layer w10: v1(4704.85,2644.7) 4704.26,2645.29 4664.48,2645.29 4658.63,2639.43 4658.63,2483.51 4667.56,2474.58 4691.02,2474.58 U2.1@4695.06,2470.54 4734.74,2470.54 4739.74,2475.54 R69.1@4739.74,2477 4739.87,2476.87 4739.87,2420.13 4739.74,2420 R70.2@4740,2420 R70.2@4735.74,2424.26
NetR72_1: R72.1 U2.2 | length 203.9
  Bottom Layer w10: R72.1@4535.53,2477 4623.6,2477 4647.81,2452.79 4647.81,2435.11 4687.18,2395.74 U2.2@4695.06,2395.74 ; R72.1@4537.03,2477 R72.1@4537.27,2477.24
NetR77_1: R77.1 R78.1 R79.1 R80.2 R81.1 | length 266.8
  Bottom Layer w10: R78.1@3535.68,1919.01 R78.1@3541.77,1919.01 ; R78.1@3546.77,1924.01 R78.1@3541.77,1919.01 ; R80.2@3569.03,1964 3569.28,1964.25 3621.78,1964.25 R81.1@3622.03,1964 3622.03,1923.5 R77.1@3618.03,1919.5 ; R77.1@3618.17,1919.01 R78.1@3541.77,1919.01 ; R77.1@3619.66,1920.5 3689,1920.5 R79.1@3695.04,1926.54
NetR82_2: R82.2 U3.3 | length 98
  Bottom Layer w10: R82.2@3678.53,2135.5 3683.53,2130.49 3697.68,2130.49 3705.87,2122.29 U3.3@3705.87,2057.1
NetR83_1: R83.1 R84.2 R85.2 R86.1 U3.4 | length 512
  Bottom Layer w10: R84.2@3773.14,2192.2 3777.16,2196.22 3833.21,2196.22 3863.06,2226.07 3863.06,2251.98 R83.1@3863.8,2252.71 ; U3.4@3792.48,2057.1 3795.36,2059.97 3812.86,2059.97 3824.06,2071.17 3824.06,2188.52 3830.03,2194.5 ; R83.1@3870.06,2255.51 3883.53,2255.51 3919.16,2219.87 R85.2@3919.16,2134.51 3918.42,2133.76 R86.1@3918.42,2066.5 ; R86.1@3914.3,2066.74 R86.1@3914.53,2066.5
NetR89_2: R89.2 R90.1 R100.1 R100.2 U4.1 | length 665.3
  Bottom Layer w10: R89.2@4300.18,2220.51 4307.68,2220.51 4312.68,2225.51 4312.68,2231.64 4318.53,2237.5 U4.1@4382.29,2237.5 ; R100.2@4332.87,2074.07 4344.68,2074.07 4443.11,2172.5 ; U4.1@4392.57,2237.5 4518.07,2363.01 R90.1@4569.18,2363.01 ; 4452.53,2172.5 4443.11,2172.5 ; 4452.76,2172.5 R100.1@4536.03,2172.5 ; U4.1@4390.16,2235.1 U4.1@4382.29,2235.1 U4.1@4390.16,2235.1 ; U4.1@4390.16,2235.1 4396.98,2228.29 4396.98,2218.63 4443.11,2172.5
NetR92_1: R92.1 R93.1 R94.1 R95.2 R96.1 | length 274.9
  Bottom Layer w10: R96.1@3434.03,2417 3503.34,2347.69 R94.1@3503.34,2295.08 ; R92.1@3441.84,2293.59 3443.33,2295.08 R94.1@3503.34,2295.08 ; R93.1@3564.83,2296.56 3563.35,2295.08 R94.1@3503.34,2295.08
NetR96_2: R96.2 U5.1 | length 129.4
  Bottom Layer w10: R96.2@3430.53,2481 3441.03,2481 3489.83,2432.2 U5.1@3539.73,2432.2
nRST: R37.1 R57.1 U1.38 | length 2104.7
  Top Layer w8: R57.1@1400,2790 v3(1400,2817.24)
  Top Layer w10: U1.38@2667.17,1882.21 2687.71,1882.21 2704.03,1898.53 v1(2750.08,1898.53)
  Signal Layer 1 w8: v3@1400.22,2817.24 1476.03,2817.24 2296.73,1996.53 2296.73,1804.08 2345.67,1755.14 2640.53,1755.14 2654.76,1769.37 2654.76,1813.55 2721.2,1879.99 2731.55,1879.99 v1(2750.08,1898.53)
R_FB: JP6.4 R18.2 | length 363.2
  Top Layer w10: JP6.4@1754.31,2101.32 2059.1,2101.32 R18.2@2100.43,2059.98
RT: R25.1 R30.2 U1.12 | length 365.9
  Top Layer w10: U1.12@2438.83,1901.9 2421.54,1901.9 2413.87,1909.56 2413.87,2004.64 2387.43,2031.08 2387.43,2144.99 2403.19,2160.75 2412.36,2160.75 R30.2@2417.36,2165.75 R25.1@2470.26,2165.75
SCL: J12.9 R27.2 R64.1 U1.6 | length 1493
  Top Layer w10: R27.2@2032.57,2700.73 2032.63,2700.79 2065.11,2700.79 ; v1(2065.04,2670.6) 2065.04,2700.73 2065.11,2700.79 ; J12.9@2200.67,3001.23 2097.33,2897.9 2097.33,2701.04 R64.1@2097.58,2700.79 2065.11,2700.79 ; U1.6@2543.16,1947.17 2543.16,1999.36 v1(2552.04,2008.24)
  Signal Layer 2 w10: v1(2065.04,2670.6) 2069.31,2666.33 2070.8,2666.33 2112.31,2624.82 2303.38,2624.82 2444.73,2483.47 2444.73,2093.71 2459.62,2078.82 2530.2,2008.24 v1(2552.04,2008.24)
SDA: J12.10 R28.2 R65.1 U1.5 | length 1440.2
  Top Layer w8: R65.1@2200.67,2701.1 J12.10@2200.67,2901.23
  Top Layer w10: v1(2154.38,2699.94) 2154.83,2700.4 2199.96,2700.4 R65.1@2200.42,2700.85 ; R65.1@2200.67,2701.1 R65.1@2200.42,2700.85 ; R28.2@2269.93,2700.85 R65.1@2200.42,2700.85 ; U1.5@2562.84,1947.17 2562.84,1983.86 2592.37,2013.39 v1@2592.37,2023.59
  Signal Layer 2 w10: v1(2154.38,2699.94) 2204.59,2649.73 2516.89,2649.73 2557.24,2609.37 2557.24,2146.6 2557.35,2146.5 2557.35,2125.89 2557.24,2125.79 2557.24,2065.74 v1(2593.31,2029.67)
SLOPE: JP8.1 R29.2 U1.9 | length 468
  Top Layer w10: U1.9@2484.1,1947.17 2484.1,2028.85 2500.64,2045.39 2500.64,2166.52 ; JP8.1@2500.64,2377.56 2500.64,2166.52 ; R29.2@2531.4,2166.52 2500.64,2166.52
SS/ATRK: C44.1 TP12.1 U1.2 | length 533.4
  Top Layer w10: U1.2@2621.9,1947.17 2621.9,1964.49 2684.02,2026.62 v1(2720.52,2026.62)
  Signal Layer 2 w10: v1(2720.52,2026.62) 2799.36,2105.46 2941.66,2105.46 3035.67,2199.46 TP12.1@3040.7,2199.46
SW1: C39.1 C55.2 C59.2 C61.2 Q1.1-2-3 Q1A.1-2-3 Q2.5-6-7-8 Q2A.5-6-7-8 R3.1 R4.1 R7.2 TP5.1 U1.23 | length 1202.7
  Top Layer w10: C39.1@2502.85,1674.78 C39.1@2503.11,1674.52 ; C39.1@2502.85,1687.37 2502.85,1711.16 U1.23@2503.71,1712.02
  Top Layer w18: 2433.41,1659.03 2446.65,1672.27 2468.85,1672.27 2482.58,1672.27 2486.85,1676.54 C39.1@2502.23,1676.54 ; v2@2482.5,1672.27 v2(2484.17,1673.94) ; 2492.75,1676.54 C39.1@2502.23,1676.54 ; C39.1@2503.73,1679.54 2503.73,1678.04 C39.1@2502.23,1676.54
  Top Layer w20: 2433.41,1632.17 2433.41,1659.03
  Signal Layer 2 w12: v3(2110,1670) 2110,1668.95 2121.98,1656.97 2121.98,958.02 2202.62,877.38 ; 2205.63,875 2327.07,875 2335,882.93 v2(2335,920)
  Bottom Layer w10: C59.2@2457.57,1664.74 2457.57,1665.95 C59.2@2463.31,1671.68 ; C59.2@2457.57,1665.36 2465.24,1673.03 v2@2480.67,1673.03 ; v2@2482.58,1672.27 2481.43,1672.27 2480.56,1673.13 2484.74,1673.94 v2(2484.17,1673.94)
  Bottom Layer w20: C59.2@2464.46,1672.25 v2@2479.89,1672.25
SW2: C40.1 C58.1 C60.2 C64.1 L1.2 Q3.5-6-7-8 Q3A.5-6-7-8 Q4.1-2-3 Q4A.1-2-3 TP6.1 U1.33 | length 240.7
  Top Layer w12: U1.33@2667.25,1783.71 2691.91,1783.71
  Top Layer w13: 2691.91,1783.71 2726.85,1748.77 2726.85,1747.85 C40.1@2734.85,1739.85
  Top Layer w20: C40.1@2734.14,1739.14 2770.64,1702.64 2770.64,1616.81
  Bottom Layer w10: v2(2808.62,1650.02) C60.2@2808.62,1666.97
SYNC: C53.1 R23.2 TP11.1 U1.3 | length 464.1
  Top Layer w10: U1.3@2602.21,1947.17 2602.21,1972.68 2667.46,2037.93 2670.06,2037.93 2677.6,2045.47 2677.6,2045.92 2691.06,2059.37 2691.06,2063.72 2696.06,2068.72 R23.2@2756.28,2068.72 2831.31,2068.72 2870.29,2107.69 TP11.1@2870.29,2219.44
SYNC1: JP2.2 R23.1 | length 2277.3
  Top Layer w8: R23.1@2757.74,2131.27 R23.1@2758.18,2131.72
  Top Layer w20: R23.1@2758.18,2131.72 v1(2758.18,2151.71)
  Signal Layer 1 w10: v1(2758.18,2151.71) 2796.81,2190.34 2796.81,2554.8 3115.16,2873.15 4323.15,2873.15 JP2.2@4450,3000
V_REF1: C93.1 J15.2 R88.1 R89.1 R91.2 U4.2 | length 600.9
  Bottom Layer w10: R91.2@4240.18,2282.99 R89.1@4292.68,2282.99 ; R88.1@4245.18,2339.01 4250.18,2344.01 R88.1@4250.18,2351.51 4250.79,2352.12 C93.1@4288.22,2352.12 R89.1@4288.22,2285.51 ; J15.2@4283,1990.03 4283,1997.95 4267.85,2013.09 4267.85,2015.35 4259.83,2023.37 4259.83,2225.87 4287.68,2253.71 4287.68,2275.51 R89.1@4292.68,2280.51 ; R89.1@4288.23,2285.5 4295.19,2285.5 R89.1@4300.18,2280.51 4336.76,2280.51 4359.34,2303.09 4382.24,2303.09 U4.2@4389.15,2310
V_REF2: R82.1 R91.1 R97.1 | length 1925.3
  Bottom Layer w10: R97.1@3372.03,2417.5 3382.03,2417.5 3382.53,2417 3382.53,2395.48 3411.47,2366.54 3411.47,2074.45 3492.67,1993.25 3492.67,1856.31 3519.42,1829.56 4094.65,1829.56 4175.18,1910.09 4175.18,2277.99 R91.1@4180.18,2282.99 ; 3412.53,2134.5 3413.53,2135.5 R82.1@3618.53,2135.5
VBUS: J12.5 R64.2 R65.2 | length 746.7
  Top Layer w8: R64.2@2097.64,2640.85 R65.2@2200.92,2640.85 2208.42,2640.85 2239.9,2609.37 2309.57,2609.37
  Top Layer w10: 2309.57,2609.37 2345.22,2645.02 2382.03,2645.02 2382.3,2645.3 2431.68,2645.3 2451,2664.62 2451,2950.9 J12.5@2400.67,3001.23
VCC1: C37.2 C89.1 C90.1 C92.1 C94.1 J13.1 R71.2 R76.1 R87.1 R88.2 U1.1 U3.5 U5.5 | length 5390.9
  Top Layer w10: U1.1@2641.58,1947.17 v1(2661.1,1947.17) 2670.93,1947.17 C37.2@2693.76,1970.01
  Signal Layer 1 w10: v1(3664.52,2386.61) 3768.49,2282.65 3768.49,1990.24 3761.53,1983.29 v1(3761.53,1979.5)
  Signal Layer 2 w10: v1(2661.1,1947.17) 2661.1,1949.91 2644.44,1966.58 2644.44,2010.99 2724.9,2091.45 2724.9,2508.16 3089.88,2873.15 4631.15,2873.15 J13.1@4755,2997
  Bottom Layer w10: U5.5@3626.34,2432.2 3628.53,2430.01 3628.53,2380 C94.1@3629.03,2379.5 ; U5.5@3627.03,2432.5 U5.5@3636.87,2432.5 ; C94.1@3630.53,2377.5 3630.53,2383.61 3633.53,2386.61 v1(3664.52,2386.61) v1@3661.84,2389.29 ; v1(3761.53,1979.5) 3789.53,1979.5 ; C90.1@3789.53,1950 3789.53,1979.5 ; U3.5@3792.48,2005.92 3792.41,2005.92 3789.53,2003.04 3789.53,1979.5 ; R87.1@3919.03,1984 3916.64,1981.61 3910.41,1981.61 3908.3,1979.5 3789.53,1979.5 ; R87.1@3920.4,1985.37 3975,1930.77 4088.83,1930.77 4134.92,1976.87 4134.92,2326.87 4159.56,2351.51 R88.2@4190.18,2351.51 4195.18,2356.51 4195.18,2372.14 4205.53,2382.5 4403.53,2382.5 C92.1@4408.53,2377.5 ; C92.1@4408.53,2370.5 C92.1@4408.53,2377.5 ; C92.1@4408.53,2378 C92.1@4408.53,2377.5 ; C92.1@4408.68,2378.15 4410.29,2379.76 4427.68,2379.76 4498.41,2450.49 4498.41,2591.37 4525.53,2618.5 R71.2@4525.53,2626 ; R71.2@4527.03,2626 4525.53,2627.5 C89.1@4525.53,2689.74 R76.1@4563.66,2689.74 4568.66,2694.74 4568.66,2718.65 4755,2904.99 J13.1@4755,2997
VCC2: C38.2 JP1.3 JP2.3 JP3.3 JP6.5 JP9.3 R33.2 TP10.1 U1.29 | length 6942.3
  Top Layer w10: U1.29@2621.98,1712.02 2623.79,1710.2 2623.79,1693.27 2630.6,1686.46 2630.6,1670 ; C38.2@2677.5,1652.02 2682.5,1657.02 v1(2682.5,1660)
  Top Layer w11: 2630.6,1670 2630.6,1668.89 2647.47,1652.02 2648.58,1652.02
  Top Layer w12: 2648.58,1652.02 C38.2@2677.5,1652.02
  Top Layer w15: R33.2@2888.51,2793.22 2886.01,2795.72 2886.01,2805.92 2868.51,2823.42 2868.51,3026.04 2933.76,3091.29 3458.71,3091.29 JP1.3@3550,3000
  Signal Layer 1 w20: TP10.1@1700,2450.86 1754.31,2396.54 JP6.5@1754.31,2201.32 ; v1(2418.56,2035.87) 2418.56,2034.79 2408.95,2025.18 2408.95,1995.59 2433.73,1970.81 2605.66,1970.81 2703.56,2068.72 2801.91,2068.72 2873.3,1997.33 2873.3,1862.47 2872.4,1861.58 2872.4,1859.83 v2@2873.3,1858.93
  Signal Layer 2 w20: v1(2418.56,2035.87) 2248.85,2035.87 2083.4,2201.32 JP6.5@1754.31,2201.32 1754.31,2396.54 TP10.1@1700,2450.86 JP9.3@1700,3000 1791.29,3091.29 3550,3091.29 ; v1(2682.5,1660) 2682.5,1708.35 2661.1,1729.75 2661.1,1797.45 2717.46,1853.8 2867.46,1853.8 v2@2871.64,1857.98 ; JP1.3@3550,3000 3550,3091.29 ; JP3.3@3950,3000 3950,3091.29 ; JP2.3@4350,3000 4258.71,3091.29 3950,3091.29 ; 3550,3091.29 3950,3091.29
  other v2: 2868.16,1859.12
VEXT: J7.1 JP4.1 | length 881.6
  Signal Layer 1 w10: JP4.1@250,2300 314.17,2364.17 314.17,2776.62 537.56,3000 J7.1@600,3000
VIN: C1.2 C2.2 C30.2 C87.2 D1.1 D2.1 J1.1 J5.1 J5.2 JP4.3 JP5.3 JP7.3 Q5.1 Q5.2 Q5.3 Q5.5-6-7-8 Q6.1 Q6.2 Q6.3 Q6.5 Q6.6 Q6.7 Q6.8 Q6.9@1118.58,1582.5 R1.1 R2.1 R5.2 R39.2 R58.2 R69.2 R78.2 R93.2 TP1.1 TP7.1 | length 9769.7
  Top Layer w20: v1(2238.45,1746.7) R5.2@2258.08,1746.7
  Signal Layer 1 w10: J5.1@200,1380 200,2350 JP4.3@250,2400 296.3,2446.3 296.3,2784.02 585.7,3073.42 826.58,3073.42 JP5.3@900,3000 971,3071 1229,3071 JP7.3@1300,3000 1370,3070 4578.14,3070 4809,2839.14 v3(4809,2477) ; v1(3541.19,1888.57) 3541.19,2065.81 3478.47,2128.53 3478.47,2205.34 3496.39,2223.26 3548.31,2223.26 v1(3564.83,2206.73)
  Signal Layer 2 w10: v1(3541.19,1888.57) 3541.95,1888.57 3554.05,1900.67 3613.25,1900.67 3987.58,2275 4280.62,2275 4482.62,2477 v3(4809,2477)
  Signal Layer 2 w12: v3(1265,1545) 1293.55,1516.45 1343.45,1516.45 1555.25,1728.25 2071.26,1728.25 2089.71,1746.7 v1(2238.45,1746.7)
  Bottom Layer w10: R78.2@3535.68,1859.01 3536.19,1859.01 3541.19,1864.01 v1(3541.19,1888.57) ; v1(3564.83,2206.73) R93.2@3564.83,2236.56
  other v1: 919.27,1167.6 410,1174.96 510,1192 778.61,1199.77 853.65,1206.64 315.47,1221.77 1117.73,1229.74 924.09,1245.68 441,1248.67 916.57,1333.98 1136.4,1389.8 849.32,1418.66 923.65,1427.64 1229.6,1446.12 1172.59,1477.25 853.6,1492.25 1118.16,1492.49 1180.91,1529.52 913.6,1536.41 1128.45,1542.38 1229.6,1542.08 913.6,1584.89 1104.44,1590.62 1102.35,1641.8 1152.87,1645.4 873.6,1780 950.44,1937.01
  other v3: 590,1135 710,1135 590,1160 710,1160 590,1185 710,1185 590,1210 710,1210 590,1235 710,1235 590,1260 710,1260 590,1285 710,1285 801,1296.38 600,1310 625,1310 650,1310 675,1310 700,1310 510,1358.35 675,1402.81 761.87,1428.11 441,1434.23 650,1453.23 144.67,1466.45 329.47,1491.45 770.29,1540.31 1162.77,1582.59 1211.84,1600.26 147.36,1607.54 250,1635.95 1243.37,1641.02 86,1704 125.13,1780 250,1840.65 125.77,1869.91 1136.4,1901.32 1190.23,1910.32 287.75,1929.21 134.36,1930.11 1069.49,1933.68 1230,1957.1 1163.37,1971.92 1100.61,1988.16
